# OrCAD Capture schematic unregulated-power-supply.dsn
size A; title: Unregulated Power Supply
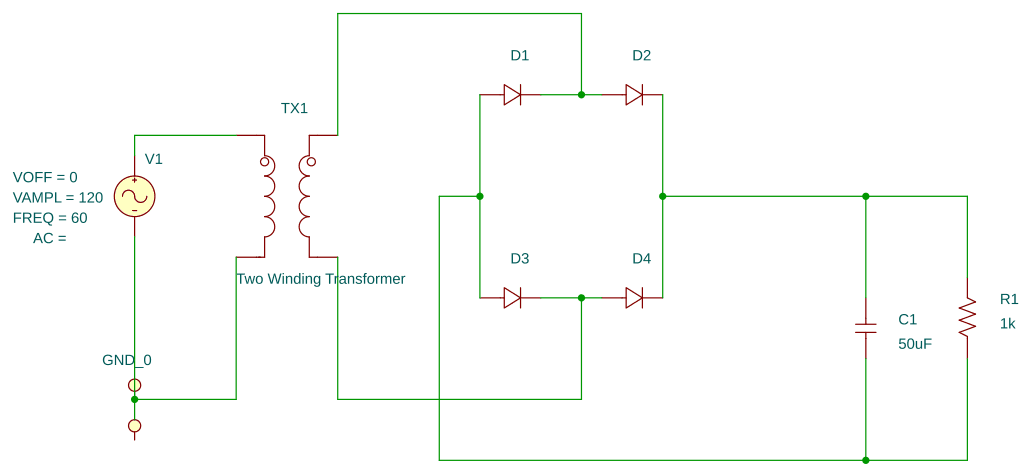
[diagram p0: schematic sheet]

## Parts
C1  50uF  [cap196]
D1  Dbreak
D2  Dbreak
D3  Dbreak
D4  Dbreak
R1  1k  [AXRC05]
TX1  Two Winding Transformer
V1  VSIN

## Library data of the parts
C1 = C
D1-D4 = Dbreak
R1 = R
TX1 = ST: AppProp: modelname=ST_Model3,LP1=1m,RP1=10m,Rs1=10m,N=0.1,LI=100n
V1 = VSIN: FREQ: 60; VAMPL: 120; VOFF: 0

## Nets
0: TX1.2 V1.2(-)
N21454: D1.1(2) D2.0(1) TX1.3
N21510: C1.1 D1.0(1) D3.0(1) R1.1
N21522: C1.2 D2.1(2) D4.1(2) R1.2
N21526: TX1.1 V1.1(+)
N21634: D3.1(2) D4.0(1) TX1.4
